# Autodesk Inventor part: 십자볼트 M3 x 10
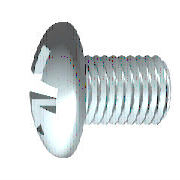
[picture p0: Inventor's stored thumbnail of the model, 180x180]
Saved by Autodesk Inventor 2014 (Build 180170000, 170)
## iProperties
IsCustomPart: 0
Created: 2012-02
Part Number: 십자볼트 M3 x 10
Material: 스테인리스강
Description: 십자 오목 머리 나사
Document SubType Name: Modeling
Standard: KS B 1023
Designer: mduedu
Standards Organization: KS
Language: ko-KR
Size Designation: A  M 3 x 10 - H
Categories: <MemberInstance><Categories><Category DisplayName="조임쇠" InternalName="e4da775c-781d-43d5-af7c-5136215cf5a6" Mnemonic="FSTN"><Category DisplayName="볼트" InternalN
Density: 1 g/cm^3
Appearance: 반광택
Author: mduedu
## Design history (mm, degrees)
workplane "Work Plane3"
sketch "스케치2"
  geometry: L1 (-3.72, 0)-(3.72, 0) reference; L2 (0, -3.72)-(0, 3.72) reference; L3 (0, 1.5)-(0, 0); L4 (0, 0)-(1.5, 0); L5 (0, 0)-(1.879, 1.879); L6 (0.253, 1.479)-(0.261, 0.456); L7 (1.479, 0.253)-(0.456, 0.261); L8 (0.253, -1.479)-(0.261, -0.456); L9 (1.479, -0.253)-(0.456, -0.261); L10 (-0.253, 1.479)-(-0.261, 0.456); L11 (-1.479, 0.253)-(-0.456, 0.261); L12 (-1.479, -0.253)-(-0.456, -0.261); L13 (-0.253, -1.479)-(-0.261, -0.456); A1 r 0.45 centre (0, 0) between (0.45, 0) and (0, 0.45); A2 r 1.5 centre (0, 0) between (1.5, 0) and (1.479, 0.253); A3 r 1.5 centre (0, 0) between (0.253, 1.479) and (0, 1.5); A4 r 1.5 centre (0, 0) between (1.479, 0.253) and (0.253, 1.479); A5 r 1.5 centre (0, 0) between (0, -1.5) and (0.253, -1.479); A6 r 1.5 centre (0, 0) between (0.253, -1.479) and (1.479, -0.253); A7 r 1.5 centre (0, 0) between (1.479, -0.253) and (1.5, 0); A8 r 1.5 centre (0, 0) between (-1.479, 0.253) and (-1.5, 0); A9 r 1.5 centre (0, 0) between (-0.253, 1.479) and (-1.479, 0.253); A10 r 1.5 centre (0, 0) between (0, 1.5) and (-0.253, 1.479); A11 r 1.5 centre (0, 0) between (-1.5, 0) and (-1.479, -0.253); A12 r 1.5 centre (0, 0) between (-1.479, -0.253) and (-0.253, -1.479); A13 r 1.5 centre (0, 0) between (-0.253, -1.479) and (0, -1.5); A14 r 0.525 centre (0, 0) between (0.525, 0) and (0, 0.525); A15 r 0.197 centre (0.457, 0.457) between (0.261, 0.456) and (0.456, 0.261); A16 r 0.197 centre (0.457, -0.457) between (0.456, -0.261) and (0.261, -0.456); A17 r 0.197 centre (-0.457, 0.457) between (-0.456, 0.261) and (-0.261, 0.456); A18 r 0.197 centre (-0.457, -0.457) between (-0.261, -0.456) and (-0.456, -0.261); 1 further point
  constraints: 38 point on circle, 22 end point, 19 symmetric about line, 18 centre point, 4 coincident, 3 collinear, 3 point on line, 3 tangent, 1 perpendicular, 21 other
  dimensions: "d4" = 45 deg angle of L5 L4; "d5" = 0.9 diameter of A1 (= 0.3 x SDM); "d6" = 3 diameter of A4 (= SDM); "d7" = 0.2525 distance from line of L6.start L3 (= 0.5 x SBR); "d14" = 1.05 diameter of A14 (= 0.35 x SDM)
extrude "슬롯" join sketch "스케치2" taper "d15" = 5 deg; stored distance "d54" = 10
revolve "절단부" stored, may be unused: angle "d56" = 90 deg
revolve "본체" stored, may be unused: angle "d18" = 90 deg
body "Solid1"
sketch "스케치1"
  geometry: L1 (10, 0)-(10, 1.5); L2 (10, 1.5)-(1, 1.5); L3 (3.962, 5.08)-(3.962, 5.08); L4 (-2.4, 0)-(-2.4, 2.59); L5 (-2.2, 1.4)-(-1.036, 0.82); L6 (-1.036, 0.82)-(-0.6, 0); L7 (-0.6, 0)-(10, 0); L8 (-5.105, 0)-(12.517, 0) reference; L9 (0, -1.016)-(0, 6.096) reference; L10 (-2.2, 1.4)-(-2.4, 1.5); L11 (-1.636, 2.657)-(-2.4, 2.59); L12 (-1.636, 2.657)-(0, 2.8); L13 (0, 2.8)-(0, 1.347); L14 (0, 1.347)-(0.693, 1.347); L15 (0.693, 1.347)-(1, 1.5); L16 (1, 1.5)-(0, 1.5); A1 r 5 centre (2.6, 0) between (-1.636, 2.657) and (-2.4, 0)
  constraints: 28 end point, 5 point on line, 4 collinear, 4 point on circle, 3 parallel, 2 perpendicular, 1 centre point, 1 horizontal, 1 tangent
  dimensions: "d1" = 3 diameter of L2 L7 (= GD); "d2" = 1.8 distance from line of L6.end L4 (= STI); "d11" = 3 diameter of L10.end L7 (= SDM); "d12" = 62 deg angle of L6 L7; "d13" = 26.5 deg angle of L5 L7; "d17" = 5.6 diameter of L12.end L7 (= KOD); "d19" = 5 deg angle of L12 L7 (= KEWI); "d20" = 2.4 distance between parallel lines of L4 L13 (= KOH); "d21" = 5 radius of A1 (= KR); "d23" = 2.6935 diameter of L14 L7 (= BDM); "d24" = 9 distance of L1.end L2.end (= GEL); "d25" = 0.30673 horizontal distance of L14.end L2.end (= GAL); "d28" = 10 distance between parallel lines of L1 L13 (= NLG)
workplane "Work Plane1"
fillet "모깎기1" dims "d29" = 1.2 (= RR)
fillet "모깎기2" dims "d16" = 0.101 (= 0.2 x SBR)
feature "스레드" dims "d8" = 9 (= GEL), "d9" = 0
chamfer "모따기1" distance "d26" = 0.30673 (= -0.5 x SPD + 0.5 x GD); stored, may be unused: second distance "d27" = 0.30683 (computed from GUL), angle "d78" = 45 deg
other parameters: "GD" = 3 (= NND) [user parameter; used in 2 equation terms], "NLG" = 10 [user parameter; used in 1 equation term], "GEL" = 9 [user parameter; used in 2 equation terms], "KOD" = 5.6 [user parameter; used in 1 equation term], "KOH" = 2.4 [user parameter; used in 2 equation terms], "SDM" = 3 [user parameter; used in 4 equation terms], "STI" = 1.8 [user parameter; used in 1 equation term], "SBR" = 0.505 [user parameter; used in 2 equation terms], "GAL" = 0.30673 (= 0.61345 x PTC) [user parameter; used in 1 equation term], "SPD" = 2.38655 (= NND - 1.2269 x PTC) [user parameter; used in 1 equation term], "KEWI" = 5 deg [user parameter; used in 1 equation term], "d3" = -2.4 (= -KOH), "d10" = 0, "KR" = 5 [user parameter; used in 1 equation term], "BDM" = 2.6935 [user parameter; used in 1 equation term], "GUL" = 0.30673 (= 0.61345 x PTC) [user parameter; used in 1 equation term], "RR" = 1.2 [user parameter; used in 1 equation term], "d79" = 0, "d80" = 0, "PTC" = 0.5 [user parameter; used in 5 equation terms], "THREADDIA" = 3 [user parameter; used in 1 equation term], "TOA" = 30 deg [user parameter], "NND" = 3 [user parameter; used in 2 equation terms], "GD1" = 2.38655 (= THREADDIA - 1.2269 x PTC) [user parameter]
